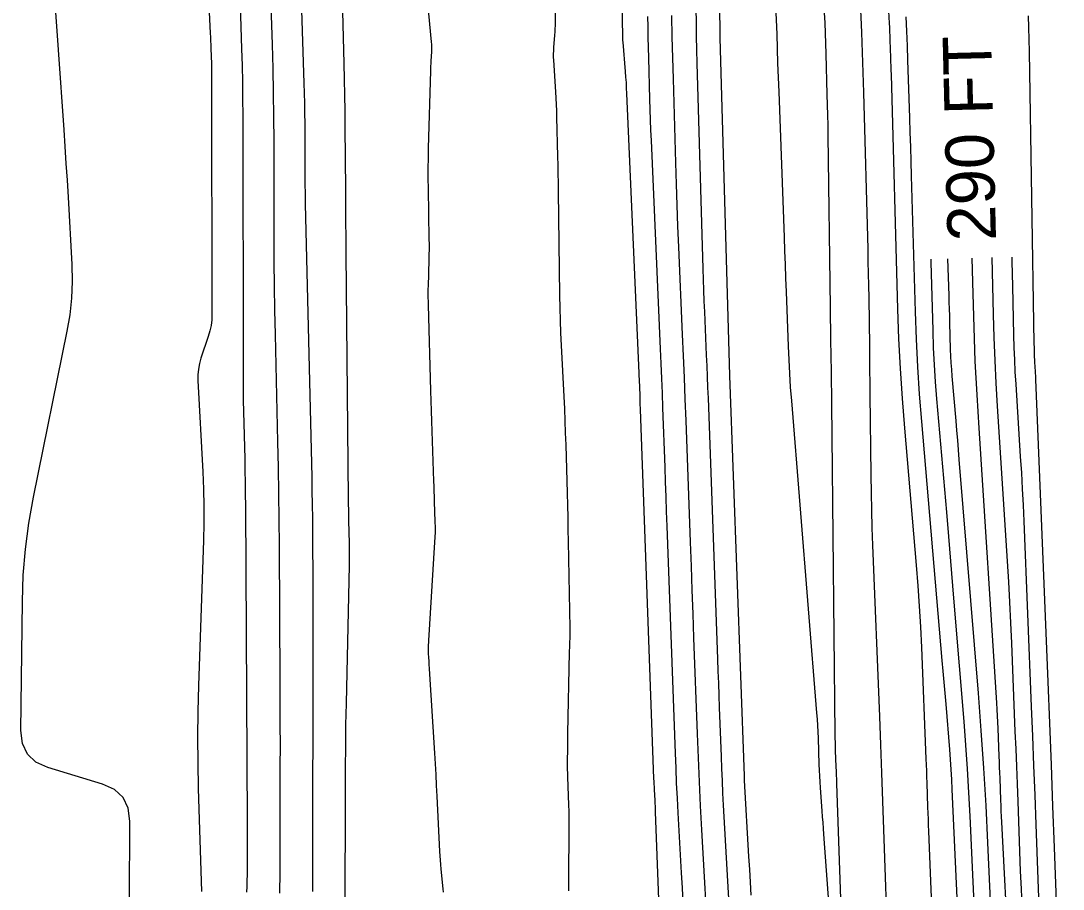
# Model space of a CAD drawing. Extents: x 1768942 to 1774819, y 723037 to 732099.
# Drawn here: x 1770739 to 1770868, y 725533.3 to 725640.7 of the extents above; entities that cross this region are included whole.
import ezdxf

# ---------------------------------------------------------------- set-up
doc = ezdxf.new("R2010")
doc.units = 0
doc.layers.add('R_Contour Annot', color=7, linetype='Continuous')
doc.layers.add('R_Contours', color=7, linetype='Continuous')

msp = doc.modelspace()

# ---------------------------------------------------------------- linework, layer by layer
at = {"layer": 'R_Contours'}
for points in [[(1770829.41, 725532.6), (1770829.31, 725534.19), (1770829.21, 725535.77), (1770829.11, 725537.36), (1770828.58, 725546.78), (1770828.58, 725546.83), (1770828.58, 725546.88), (1770828.58, 725546.93), (1770828.58, 725546.97), (1770828.56, 725547.36), (1770826.76, 725596.84), (1770826.76, 725596.86), (1770825.56, 725638.66), (1770825.56, 725638.79), (1770825.56, 725638.92), (1770825.56, 725639.05), (1770825.55, 725639.17), (1770825.55, 725639.68), (1770825.55, 725639.81), (1770825.55, 725639.94), (1770825.54, 725640.07), (1770825.54, 725640.19), (1770823.89, 725689.37)], [(1770812.83, 725687.64), (1770813.44, 725640.6), (1770813.44, 725640.39), (1770813.44, 725640.18), (1770813.44, 725639.97), (1770813.45, 725639.76), (1770813.46, 725638.93), (1770813.46, 725638.73), (1770813.47, 725638.52), (1770813.48, 725638.31), (1770813.5, 725638.1), (1770813.8, 725634.46), (1770813.85, 725633.78), (1770813.9, 725633.1), (1770813.94, 725632.43), (1770813.97, 725631.75), (1770815.49, 725597.16), (1770815.5, 725596.79), (1770815.52, 725596.42), (1770815.53, 725596.04), (1770815.55, 725595.67), (1770815.6, 725594.17), (1770815.63, 725593.43), (1770815.66, 725592.68), (1770817.32, 725547.01), (1770817.33, 725546.67), (1770817.35, 725546.33), (1770817.37, 725545.99), (1770817.38, 725545.65), (1770817.46, 725544.29), (1770817.48, 725543.95), (1770817.5, 725543.6), (1770817.51, 725543.26), (1770817.52, 725542.92), (1770818.82, 725508.3)], [(1770772.81, 725670.48), (1770774.04, 725633.04), (1770774.08, 725631.8), (1770774.1, 725630.55), (1770774.12, 725629.31), (1770774.13, 725628.06), (1770774.13, 725623.08), (1770774.14, 725621.83), (1770774.15, 725620.59), (1770774.17, 725619.34), (1770774.2, 725618.1), (1770775, 725584.29), (1770775.03, 725582.6), (1770775.06, 725580.9), (1770775.08, 725579.2), (1770775.1, 725577.5), (1770775.13, 725570.7), (1770775.14, 725569), (1770775.14, 725567.3), (1770775.14, 725565.6), (1770775.14, 725563.9), (1770775.09, 725534.82), (1770775.08, 725533.06)], [(1770761.53, 725658.48), (1770762.44, 725639.21), (1770762.46, 725638.73), (1770762.48, 725638.26), (1770762.5, 725637.78), (1770762.52, 725637.31), (1770762.58, 725635.41), (1770762.59, 725634.93), (1770762.6, 725634.45), (1770762.61, 725633.98), (1770762.61, 725633.5), (1770762.65, 725604.48), (1770762.62, 725603.77), (1770762.53, 725603.07), (1770762.39, 725602.39), (1770762.19, 725601.71), (1770761.29, 725599.01), (1770761.09, 725598.34), (1770760.97, 725597.65), (1770760.9, 725596.95), (1770760.91, 725596.25), (1770761.51, 725584.95), (1770761.6, 725582.83), (1770761.64, 725580.71), (1770761.64, 725578.59), (1770761.59, 725576.46), (1770760.98, 725558.51), (1770760.9, 725555.33), (1770760.87, 725552.15), (1770760.89, 725548.97), (1770760.96, 725545.79), (1770761.37, 725533.07)], [(1770769.49, 725655.81), (1770770.09, 725637.83), (1770770.18, 725634.84), (1770770.24, 725631.85), (1770770.28, 725628.86), (1770770.29, 725625.87), (1770770.31, 725613.91), (1770770.32, 725610.92), (1770770.35, 725607.93), (1770770.39, 725604.94), (1770770.46, 725601.95), (1770770.77, 725588.69), (1770770.84, 725585.48), (1770770.89, 725582.27), (1770770.93, 725579.07), (1770770.96, 725575.86), (1770771.05, 725558.93), (1770771.06, 725556.32), (1770771.06, 725553.71), (1770771.07, 725551.1), (1770771.06, 725548.5), (1770771.04, 725538.06), (1770771.03, 725535.46), (1770770.99, 725532.85)], [(1770779.13, 725529.99), (1770779.16, 725545.69), (1770779.17, 725548.34), (1770779.2, 725550.99), (1770779.23, 725553.65), (1770779.29, 725556.3), (1770779.68, 725573.41), (1770779.69, 725574.09), (1770779.69, 725574.78), (1770779.68, 725575.46), (1770779.67, 725576.15), (1770779.6, 725578.89), (1770779.58, 725579.58), (1770779.57, 725580.26), (1770779.56, 725580.95), (1770779.55, 725581.63), (1770779.26, 725611.99), (1770779.25, 725613.95), (1770779.23, 725615.91), (1770779.21, 725617.87), (1770779.2, 725619.82), (1770779.14, 725627.65), (1770779.13, 725629.61), (1770779.1, 725631.57), (1770779.06, 725633.52), (1770779.02, 725635.48), (1770778.57, 725653.2)], [(1770788.57, 725650.92), (1770789.79, 725638.13), (1770789.82, 725637.83), (1770789.83, 725637.53), (1770789.83, 725637.23), (1770789.81, 725636.94), (1770789.74, 725635.75), (1770789.72, 725635.45), (1770789.7, 725635.15), (1770789.69, 725634.85), (1770789.68, 725634.55), (1770789.42, 725625), (1770789.39, 725623.75), (1770789.38, 725622.5), (1770789.38, 725621.24), (1770789.4, 725619.99), (1770789.51, 725613.73), (1770789.52, 725613.11), (1770789.52, 725612.48), (1770789.51, 725611.86), (1770789.49, 725611.23), (1770789.39, 725607.85), (1770789.38, 725607.67), (1770789.38, 725607.48), (1770789.38, 725607.3), (1770789.38, 725607.11), (1770789.38, 725606.37), (1770789.39, 725606.19), (1770789.39, 725606), (1770789.39, 725605.82), (1770789.4, 725605.63), (1770789.71, 725594.97), (1770789.74, 725593.73), (1770789.78, 725592.49), (1770789.82, 725591.24), (1770789.87, 725590), (1770790.09, 725583.8), (1770790.11, 725583.17), (1770790.13, 725582.54), (1770790.15, 725581.91), (1770790.17, 725581.28), (1770790.25, 725578.76), (1770790.26, 725578.13), (1770790.26, 725577.5), (1770790.24, 725576.87), (1770790.21, 725576.24), (1770789.45, 725564.11), (1770789.45, 725563.95), (1770789.44, 725563.79), (1770789.43, 725563.62), (1770789.43, 725563.46), (1770789.42, 725562.81), (1770789.42, 725562.64), (1770789.42, 725562.48), (1770789.43, 725562.32), (1770789.44, 725562.16), (1770789.49, 725561.36), (1770789.5, 725561.17), (1770789.51, 725560.98), (1770789.52, 725560.8), (1770789.54, 725560.61), (1770790.19, 725550.15), (1770790.28, 725548.83), (1770790.35, 725547.51), (1770790.42, 725546.18), (1770790.49, 725544.86), (1770790.82, 725538.01), (1770790.85, 725537.46), (1770790.89, 725536.91), (1770790.93, 725536.37), (1770790.98, 725535.82), (1770791.23, 725533.4), (1770791.27, 725532.96)], [(1770752.44, 725531.94), (1770752.47, 725541.76), (1770752.27, 725543.37), (1770751.64, 725544.67), (1770750.58, 725545.66), (1770749.1, 725546.33), (1770742.33, 725548.39), (1770740.86, 725549.06), (1770739.81, 725550.05), (1770739.18, 725551.34), (1770738.99, 725552.96), (1770739.18, 725568.93), (1770739.29, 725572.18), (1770739.56, 725575.4), (1770739.98, 725578.61), (1770740.55, 725581.81), (1770744.74, 725602.34), (1770745.09, 725604.39), (1770745.31, 725606.45), (1770745.39, 725608.52), (1770745.34, 725610.6), (1770744.87, 725618.94), (1770744.75, 725621.03), (1770744.62, 725623.11), (1770744.49, 725625.2), (1770744.35, 725627.28), (1770742.97, 725647.08)], [(1770766.04, 725645.54), (1770766.31, 725637.28), (1770766.37, 725635.22), (1770766.41, 725633.15), (1770766.44, 725631.09), (1770766.45, 725629.02), (1770766.49, 725598.18), (1770766.5, 725596.73), (1770766.51, 725595.28), (1770766.53, 725593.82), (1770766.56, 725592.37), (1770766.7, 725586.56), (1770766.73, 725585.11), (1770766.76, 725583.65), (1770766.77, 725582.2), (1770766.79, 725580.75), (1770766.99, 725541.56), (1770766.99, 725540.84), (1770767, 725540.12), (1770767, 725539.41), (1770767, 725538.69), (1770766.99, 725535.82), (1770766.99, 725535.11), (1770766.98, 725534.39), (1770766.96, 725533.67), (1770766.94, 725532.96)], [(1770806.84, 725533.13), (1770806.84, 725533.91), (1770806.84, 725534.68), (1770806.87, 725540.78), (1770806.87, 725541.52), (1770806.87, 725542.25), (1770806.85, 725542.99), (1770806.83, 725543.72), (1770806.7, 725547.24), (1770806.68, 725547.69), (1770806.67, 725548.14), (1770806.67, 725548.58), (1770806.67, 725549.03), (1770806.68, 725550.82), (1770806.68, 725551.27), (1770806.69, 725551.71), (1770806.69, 725552.16), (1770806.7, 725552.61), (1770806.92, 725562.66), (1770806.92, 725562.91), (1770806.93, 725563.16), (1770806.94, 725563.41), (1770806.95, 725563.65), (1770806.99, 725564.64), (1770807, 725564.89), (1770807, 725565.13), (1770807, 725565.38), (1770807, 725565.63), (1770806.79, 725576.35), (1770806.76, 725577.84), (1770806.73, 725579.33), (1770806.69, 725580.83), (1770806.65, 725582.32), (1770806.48, 725588.29), (1770806.43, 725589.79), (1770806.37, 725591.28), (1770806.31, 725592.77), (1770806.24, 725594.26), (1770805.92, 725600.59), (1770805.85, 725602.14), (1770805.79, 725603.69), (1770805.75, 725605.24), (1770805.72, 725606.79), (1770805.55, 725619.68), (1770805.53, 725620.75), (1770805.51, 725621.83), (1770805.49, 725622.9), (1770805.46, 725623.97), (1770805.35, 725628.83), (1770805.32, 725629.61), (1770805.29, 725630.4), (1770805.25, 725631.18), (1770805.21, 725631.96), (1770804.96, 725635.88), (1770804.94, 725636.27), (1770804.94, 725636.66), (1770804.95, 725637.05), (1770804.97, 725637.43), (1770805.1, 725638.98), (1770805.13, 725639.37), (1770805.15, 725639.76), (1770805.17, 725640.15), (1770805.17, 725640.54), (1770805.21, 725646.23)], [(1770842.89, 725643.04), (1770843.06, 725639.32), (1770843.19, 725635.59), (1770843.31, 725631.86), (1770843.82, 725612.49), (1770843.85, 725610.99), (1770843.89, 725609.5), (1770843.91, 725608), (1770843.94, 725606.5), (1770844.02, 725600.5), (1770844.04, 725599), (1770844.06, 725597.51), (1770844.08, 725596.01), (1770844.09, 725594.51), (1770844.2, 725584.53), (1770844.23, 725582.37), (1770844.28, 725580.21), (1770844.34, 725578.05), (1770844.42, 725575.89), (1770845.27, 725554.68), (1770845.4, 725551.2), (1770845.54, 725547.71), (1770845.66, 725544.22), (1770845.79, 725540.73), (1770846.32, 725525.38)], [(1770822.55, 725642.21), (1770822.57, 725640.53), (1770822.6, 725638.85), (1770822.63, 725637.17), (1770822.68, 725635.49), (1770823.41, 725610.08), (1770823.45, 725608.74), (1770823.49, 725607.41), (1770823.54, 725606.07), (1770823.6, 725604.74), (1770823.83, 725599.41), (1770823.89, 725598.07), (1770823.94, 725596.74), (1770824, 725595.4), (1770824.05, 725594.07), (1770825.22, 725561.82), (1770825.28, 725560.31), (1770825.33, 725558.8), (1770825.39, 725557.29), (1770825.44, 725555.79), (1770825.66, 725549.76), (1770825.72, 725548.25), (1770825.79, 725546.74), (1770825.86, 725545.23), (1770825.94, 725543.73), (1770827.81, 725510.46)], [(1770832.42, 725642.64), (1770832.55, 725639.08), (1770832.67, 725635.52), (1770832.8, 725631.96), (1770833.47, 725613.99), (1770833.53, 725612.3), (1770833.59, 725610.61), (1770833.66, 725608.93), (1770833.72, 725607.24), (1770833.97, 725600.5), (1770834.04, 725598.81), (1770834.13, 725597.13), (1770834.24, 725595.44), (1770834.37, 725593.76), (1770837.5, 725555.15), (1770837.56, 725554.37), (1770837.6, 725553.59), (1770837.64, 725552.81), (1770837.67, 725552.02), (1770837.78, 725548.77), (1770837.81, 725548.05), (1770837.84, 725547.33), (1770837.88, 725546.61), (1770837.93, 725545.89), (1770838.14, 725543.01), (1770838.2, 725542.29), (1770838.25, 725541.58), (1770838.3, 725540.86), (1770838.35, 725540.14), (1770841.49, 725497.47)], [(1770841.69, 725497.67), (1770840.01, 725546.42), (1770839.99, 725546.93), (1770839.97, 725547.43), (1770839.95, 725547.94), (1770839.93, 725548.45), (1770839.85, 725550.48), (1770839.83, 725550.99), (1770839.82, 725551.5), (1770839.81, 725552.01), (1770839.8, 725552.52), (1770839.41, 725589.38), (1770839.37, 725593.35), (1770839.32, 725597.32), (1770839.27, 725601.3), (1770839.22, 725605.27), (1770838.93, 725626.56), (1770838.91, 725627.82), (1770838.88, 725629.09), (1770838.86, 725630.35), (1770838.82, 725631.62), (1770838.69, 725636.68), (1770838.65, 725637.95), (1770838.61, 725639.22), (1770838.55, 725640.48), (1770838.48, 725641.75)], [(1770853.04, 725499.4), (1770851.38, 725540.51), (1770851.35, 725541.25), (1770851.33, 725542), (1770851.3, 725542.75), (1770851.27, 725543.5), (1770851.17, 725546.49), (1770851.14, 725547.23), (1770851.12, 725547.98), (1770851.09, 725548.73), (1770851.06, 725549.47), (1770850.51, 725563.25), (1770850.39, 725565.79), (1770850.24, 725568.33), (1770850.07, 725570.87), (1770849.86, 725573.41), (1770848.4, 725590.37), (1770848.11, 725594.04), (1770847.87, 725597.72), (1770847.69, 725601.4), (1770847.56, 725605.08), (1770846.75, 725634.1), (1770846.73, 725634.63), (1770846.72, 725635.16), (1770846.7, 725635.69), (1770846.68, 725636.22), (1770846.61, 725638.34), (1770846.59, 725638.87), (1770846.57, 725639.4), (1770846.55, 725639.93), (1770846.52, 725640.46), (1770846.39, 725642.68)], [(1770820.97, 725531.65), (1770820.88, 725533.5), (1770820.78, 725535.35), (1770820.36, 725542.76), (1770820.26, 725544.61), (1770820.17, 725546.47), (1770820.09, 725548.32), (1770820.02, 725550.17), (1770819, 725578.22), (1770818.93, 725580.05), (1770818.86, 725581.88), (1770818.8, 725583.71), (1770818.73, 725585.54), (1770818.46, 725592.86), (1770818.4, 725594.69), (1770818.32, 725596.52), (1770818.25, 725598.35), (1770818.17, 725600.18), (1770817.04, 725625.96), (1770816.99, 725627.23), (1770816.94, 725628.51), (1770816.89, 725629.78), (1770816.85, 725631.06), (1770816.71, 725636.16), (1770816.68, 725637.44), (1770816.65, 725638.71), (1770816.63, 725639.99), (1770816.61, 725641.27)], [(1770824.15, 725525.43), (1770823.3, 725540.67), (1770823.14, 725543.64), (1770822.99, 725546.6), (1770822.86, 725549.57), (1770822.75, 725552.54), (1770822.31, 725564.41), (1770822.21, 725567.38), (1770822.1, 725570.34), (1770821.99, 725573.31), (1770821.88, 725576.28), (1770821.33, 725591.3), (1770821.23, 725593.96), (1770821.13, 725596.63), (1770821.02, 725599.3), (1770820.91, 725601.96), (1770820.43, 725612.75), (1770820.32, 725615.36), (1770820.22, 725617.96), (1770820.13, 725620.56), (1770820.06, 725623.16), (1770819.76, 725633.58), (1770819.69, 725636.18), (1770819.63, 725638.78), (1770819.59, 725641.39)], [(1770848.54, 725641.25), (1770848.62, 725639.46), (1770848.7, 725637.67), (1770848.76, 725635.88), (1770849, 725628.73), (1770849.05, 725626.94), (1770849.11, 725625.14), (1770849.16, 725623.35), (1770849.21, 725621.56), (1770849.68, 725604.75), (1770849.8, 725601.35), (1770849.97, 725597.96), (1770850.19, 725594.57), (1770850.46, 725591.18), (1770853.01, 725561.64), (1770853.13, 725560.29), (1770853.24, 725558.94), (1770853.35, 725557.59), (1770853.47, 725556.24), (1770853.93, 725550.6), (1770854.02, 725549.36), (1770854.11, 725548.13), (1770854.18, 725546.89), (1770854.24, 725545.65), (1770856.33, 725500.05)], [(1770863.7, 725641.37), (1770863.74, 725639.9), (1770863.78, 725638.43), (1770863.81, 725636.96), (1770864.4, 725600.84), (1770864.4, 725600.65), (1770864.41, 725600.46), (1770864.41, 725600.26), (1770864.41, 725600.07), (1770864.43, 725599.3), (1770864.44, 725599.11), (1770864.45, 725598.91), (1770864.46, 725598.72), (1770864.47, 725598.53), (1770864.54, 725597.39), (1770864.56, 725597.13), (1770864.57, 725596.88), (1770864.58, 725596.63), (1770864.59, 725596.37), (1770866.1, 725558.99), (1770866.31, 725553.86), (1770866.51, 725548.73), (1770866.7, 725543.61), (1770866.9, 725538.48), (1770868.01, 725508.51)], [(1770851.62, 725611.26), (1770851.63, 725610.89), (1770851.86, 725602.43), (1770851.94, 725600.31), (1770852.04, 725598.2), (1770852.18, 725596.09), (1770852.35, 725593.98), (1770853.56, 725579.98), (1770853.82, 725576.94), (1770854.07, 725573.91), (1770854.33, 725570.87), (1770854.58, 725567.83), (1770855.7, 725554.09), (1770855.93, 725551.16), (1770856.13, 725548.22), (1770856.3, 725545.29), (1770856.45, 725542.35), (1770858.23, 725503.57)], [(1770853.7, 725611.31), (1770853.85, 725606.77), (1770853.88, 725605.94), (1770853.9, 725605.11), (1770853.93, 725604.27), (1770853.95, 725603.44), (1770854.04, 725600.11), (1770854.07, 725599.27), (1770854.11, 725598.44), (1770854.17, 725597.61), (1770854.23, 725596.78), (1770854.71, 725591.26), (1770854.81, 725590.07), (1770854.92, 725588.87), (1770855.02, 725587.68), (1770855.11, 725586.48), (1770857.48, 725557.59), (1770857.84, 725552.96), (1770858.15, 725548.32), (1770858.43, 725543.69), (1770858.66, 725539.05), (1770860.22, 725505.1)], [(1770862.15, 725508.3), (1770860.42, 725541.64), (1770860.38, 725542.32), (1770860.35, 725543), (1770860.32, 725543.68), (1770860.3, 725544.35), (1770860.2, 725547.07), (1770860.17, 725547.74), (1770860.14, 725548.42), (1770860.12, 725549.1), (1770860.09, 725549.78), (1770859.95, 725553.2), (1770859.92, 725553.99), (1770859.88, 725554.79), (1770859.84, 725555.58), (1770859.79, 725556.38), (1770857.6, 725590.34), (1770857.35, 725594.5), (1770857.14, 725598.66), (1770856.98, 725602.82), (1770856.86, 725606.98), (1770856.76, 725611.38)], [(1770862.93, 725531.24), (1770862.84, 725533.4), (1770862.75, 725535.56), (1770862.43, 725544.2), (1770862.35, 725546.36), (1770862.27, 725548.53), (1770862.18, 725550.69), (1770862.09, 725552.85), (1770861.66, 725563.75), (1770861.55, 725566.28), (1770861.42, 725568.82), (1770861.28, 725571.35), (1770861.12, 725573.89), (1770859.89, 725593.07), (1770859.72, 725595.91), (1770859.58, 725598.74), (1770859.47, 725601.58), (1770859.39, 725604.42), (1770859.22, 725611.45)], [(1770865.34, 725523.24), (1770864.66, 725541.34), (1770864.53, 725544.98), (1770864.39, 725548.63), (1770864.24, 725552.27), (1770864.1, 725555.92), (1770863.17, 725578.85), (1770863.09, 725580.85), (1770862.99, 725582.85), (1770862.88, 725584.85), (1770862.75, 725586.84), (1770862.18, 725595.8), (1770862.09, 725597.31), (1770862.01, 725598.83), (1770861.95, 725600.34), (1770861.91, 725601.86), (1770861.77, 725607.93), (1770861.73, 725609.44), (1770861.7, 725610.96), (1770861.69, 725611.51)]]:
    msp.add_lwpolyline(points, dxfattribs=at)

# ---------------------------------------------------------------- texts
at = {"layer": 'R_Contour Annot'}
msp.add_text('290 FT', height=6, rotation=91.4139, dxfattribs=at).set_placement((1770859.71, 725613.56))

doc.saveas('drawing.dxf')
